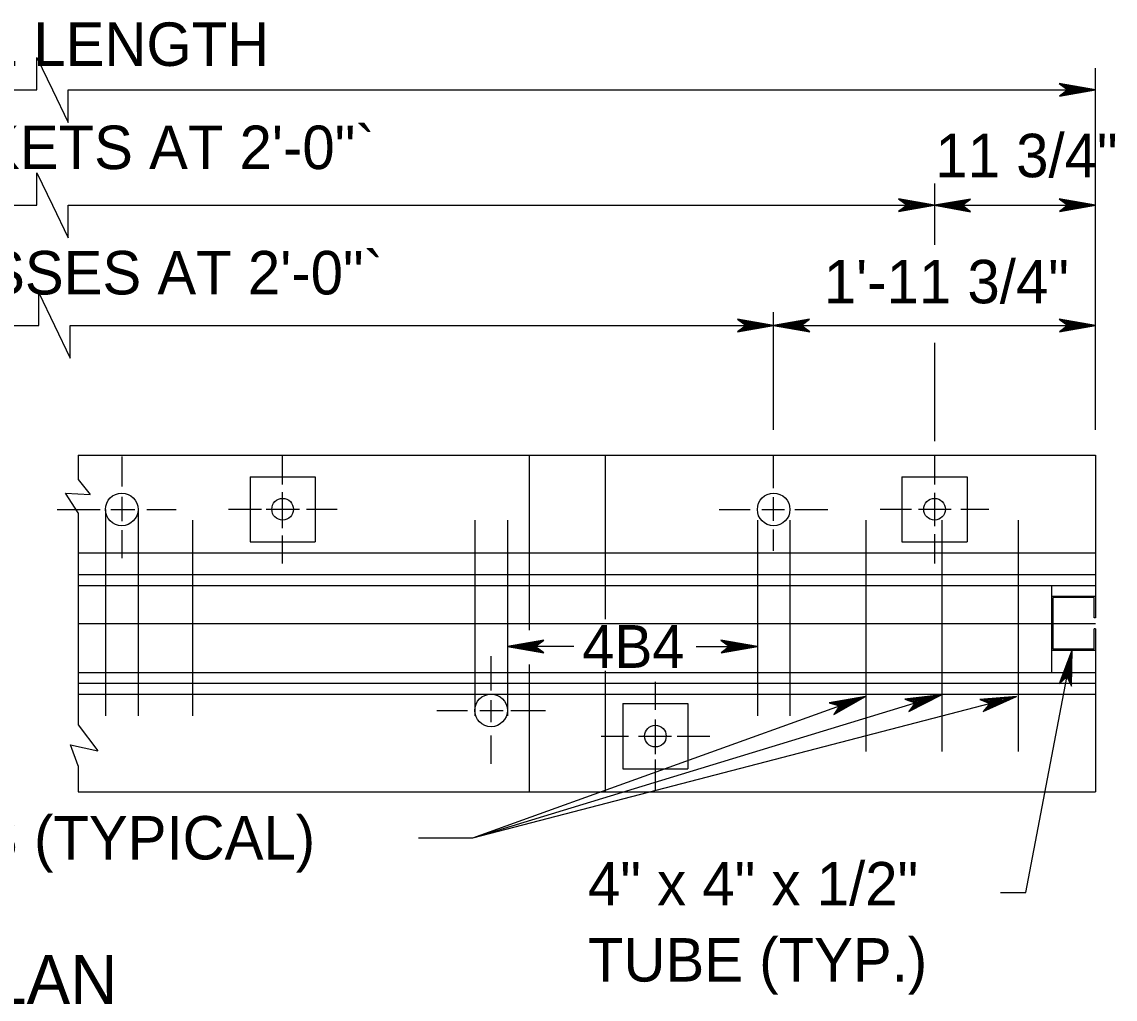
# Model space of a CAD drawing. Extents: x 499883 to 500983, y 499104 to 499764.
# Drawn here: x 500394.2 to 500494.8, y 499311.2 to 499401.1 of the extents above; entities that cross this region are included whole.
import ezdxf

# ---------------------------------------------------------------- set-up
doc = ezdxf.new("R2010")
doc.units = 0
for name, color, linetype in [('1', 7, 'Continuous'), ('24', 7, 'Continuous'), ('5', 7, 'Continuous')]:
    doc.layers.add(name, color=color, linetype=linetype)

msp = doc.modelspace()

# ---------------------------------------------------------------- linework, layer by layer
at = {"layer": '1'}
for p, q in [((500395.61, 499394.84), (500395.61, 499397.84)), ((500395.61, 499397.84), (500397.05, 499394.84)), ((500397.05, 499394.84), (500398.49, 499391.84)), ((500398.49, 499391.84), (500398.49, 499394.84)), ((500395.61, 499384.23), (500395.61, 499387.22)), ((500395.61, 499387.22), (500397.05, 499384.23)), ((500397.05, 499384.23), (500398.49, 499381.23)), ((500398.49, 499381.23), (500398.49, 499384.23)), ((500395.79, 499373.17), (500395.79, 499376.17)), ((500395.79, 499376.17), (500397.23, 499373.17)), ((500397.23, 499373.17), (500398.68, 499370.17)), ((500398.68, 499370.17), (500398.68, 499373.17)), ((500418.22, 499358.54), (500418.22, 499361.25)), ((500418.22, 499354.52), (500418.22, 499357.85)), ((500413.23, 499356.26), (500416.26, 499356.26)), ((500416.71, 499356.26), (500419.77, 499356.26)), ((500420.41, 499356.26), (500423.22, 499356.26)), ((500473.18, 499356.26), (500476.07, 499356.26)), ((500476.71, 499356.26), (500479.72, 499356.26)), ((500480.59, 499356.26), (500483.17, 499356.26)), ((500418.22, 499351.26), (500418.22, 499353.84)), ((500452.5, 499337.8), (500452.5, 499340.39)), ((500452.5, 499333.74), (500452.5, 499336.93)), ((500447.51, 499335.39), (500450.04, 499335.39)), ((500450.95, 499335.39), (500453.97, 499335.39)), ((500454.51, 499335.39), (500457.5, 499335.39)), ((500452.5, 499330.39), (500452.5, 499333.24))]:
    msp.add_line(p, q, dxfattribs=at)
at = {"layer": '24'}
for points in [[(500492.98, 499394.84), (500489.65, 499395.43), (500490.45, 499394.84), (500489.67, 499394.26), (500492.98, 499394.84), (500492.76, 499394.84), (500489.75, 499395.39), (500490.51, 499394.84), (500489.8, 499394.31), (500492.64, 499394.83), (500492.53, 499394.84), (500489.95, 499395.3), (500490.53, 499394.84), (500489.93, 499394.38), (500492.48, 499394.84), (500492.37, 499394.83), (500490.11, 499395.23), (500490.55, 499394.84), (500490.1, 499394.44), (500492.04, 499394.83), (500491.86, 499394.83), (500490.28, 499395.15), (500490.59, 499394.85), (500490.26, 499394.52), (500491.82, 499394.84), (500491.65, 499394.85), (500490.46, 499395.06), (500490.69, 499394.83), (500490.44, 499394.6), (500491.48, 499394.84), (500491.32, 499394.86), (500490.6, 499395), (500490.72, 499394.84), (500490.53, 499394.66), (500491.23, 499394.84), (500490.76, 499394.95), (500490.83, 499394.83), (500490.63, 499394.7), (500491.11, 499394.83), (500490.81, 499394.9), (500490.93, 499394.8), (500490.79, 499394.74), (500490.93, 499394.84), (500490.86, 499394.85)], [(500478.18, 499384.23), (500474.85, 499384.81), (500475.65, 499384.23), (500474.87, 499383.65), (500478.18, 499384.23), (500477.96, 499384.22), (500474.95, 499384.77), (500475.71, 499384.22), (500475, 499383.69), (500477.84, 499384.21), (500477.73, 499384.23), (500475.15, 499384.68), (500475.73, 499384.22), (500475.13, 499383.77), (500477.68, 499384.23), (500477.56, 499384.21), (500475.31, 499384.62), (500475.75, 499384.23), (500475.3, 499383.82), (500477.24, 499384.21), (500477.06, 499384.21), (500475.48, 499384.53), (500475.78, 499384.24), (500475.45, 499383.91), (500477.02, 499384.23), (500476.85, 499384.24), (500475.66, 499384.44), (500475.89, 499384.21), (500475.64, 499383.98), (500476.68, 499384.23), (500476.51, 499384.24), (500475.8, 499384.38), (500475.92, 499384.22), (500475.72, 499384.04), (500476.43, 499384.23), (500475.96, 499384.34), (500476.03, 499384.21), (500475.83, 499384.08), (500476.31, 499384.21), (500476.01, 499384.29), (500476.13, 499384.19), (500475.99, 499384.13), (500476.13, 499384.22), (500476.06, 499384.24)], [(500478.18, 499384.23), (500481.5, 499383.64), (500480.71, 499384.23), (500481.48, 499384.8), (500478.18, 499384.23), (500478.4, 499384.23), (500481.41, 499383.68), (500480.64, 499384.23), (500481.35, 499384.76), (500478.52, 499384.24), (500478.63, 499384.23), (500481.21, 499383.77), (500480.63, 499384.23), (500481.22, 499384.68), (500478.68, 499384.23), (500478.79, 499384.24), (500481.04, 499383.84), (500480.6, 499384.23), (500481.05, 499384.63), (500479.11, 499384.24), (500479.3, 499384.24), (500480.87, 499383.92), (500480.57, 499384.22), (500480.9, 499384.55), (500479.33, 499384.23), (500479.51, 499384.22), (500480.69, 499384.01), (500480.47, 499384.24), (500480.71, 499384.47), (500479.67, 499384.23), (500479.84, 499384.21), (500480.55, 499384.07), (500480.43, 499384.23), (500480.63, 499384.41), (500479.92, 499384.23), (500480.39, 499384.12), (500480.32, 499384.24), (500480.53, 499384.37), (500480.04, 499384.24), (500480.35, 499384.17), (500480.22, 499384.27), (500480.37, 499384.33), (500480.22, 499384.23), (500480.3, 499384.22)], [(500438.89, 499343.63), (500442.24, 499343.04), (500441.44, 499343.63), (500442.23, 499344.22), (500438.89, 499343.63), (500439.12, 499343.64), (500442.15, 499343.09), (500441.38, 499343.64), (500442.09, 499344.17), (500439.24, 499343.65), (500439.35, 499343.63), (500441.95, 499343.17), (500441.36, 499343.64), (500441.96, 499344.1), (500439.4, 499343.63), (500439.51, 499343.65), (500441.78, 499343.24), (500441.34, 499343.63), (500441.79, 499344.04), (500439.83, 499343.65), (500440.02, 499343.65), (500441.61, 499343.33), (500441.3, 499343.63), (500441.64, 499343.96), (500440.06, 499343.63), (500440.24, 499343.62), (500441.43, 499343.42), (500441.2, 499343.65), (500441.45, 499343.88), (500440.4, 499343.63), (500440.57, 499343.62), (500441.29, 499343.48), (500441.17, 499343.64), (500441.36, 499343.82), (500440.66, 499343.63), (500441.12, 499343.52), (500441.06, 499343.65), (500441.26, 499343.78), (500440.77, 499343.65), (500441.08, 499343.57), (500440.95, 499343.68), (500441.1, 499343.74), (500440.95, 499343.64), (500441.03, 499343.63)], [(500461.88, 499343.63), (500458.53, 499344.23), (500459.33, 499343.63), (500458.54, 499343.05), (500461.88, 499343.63), (500461.65, 499343.63), (500458.62, 499344.18), (500459.39, 499343.63), (500458.68, 499343.1), (500461.53, 499343.62), (500461.42, 499343.63), (500458.82, 499344.1), (500459.41, 499343.63), (500458.81, 499343.17), (500461.37, 499343.64), (500461.26, 499343.62), (500458.99, 499344.03), (500459.43, 499343.64), (500458.98, 499343.23), (500460.94, 499343.62), (500460.75, 499343.62), (500459.16, 499343.94), (500459.47, 499343.64), (500459.13, 499343.31), (500460.71, 499343.63), (500460.53, 499343.65), (500459.34, 499343.85), (500459.57, 499343.62), (500459.32, 499343.39), (500460.37, 499343.63), (500460.2, 499343.65), (500459.48, 499343.79), (500459.6, 499343.63), (500459.41, 499343.45), (500460.11, 499343.64), (500459.65, 499343.75), (500459.71, 499343.62), (500459.51, 499343.49), (500460, 499343.62), (500459.69, 499343.69), (500459.82, 499343.59), (500459.67, 499343.53), (500459.82, 499343.63), (500459.74, 499343.64)]]:
    msp.add_lwpolyline(points, dxfattribs=at)
at = {"layer": '5'}
for p, q in [((500492.98, 499363.56), (500492.98, 499396.84)), ((500301.12, 499394.84), (500395.61, 499394.84)), ((500398.49, 499394.84), (500492.98, 499394.84)), ((500478.18, 499386.22), (500478.18, 499380.58)), ((500316.11, 499384.23), (500395.61, 499384.23)), ((500398.49, 499384.23), (500478.18, 499384.23)), ((500478.18, 499384.23), (500492.98, 499384.23)), ((500463.38, 499363.56), (500463.38, 499374.39)), ((500331.09, 499373.17), (500395.79, 499373.17)), ((500398.68, 499373.17), (500463.38, 499373.17)), ((500463.38, 499373.17), (500492.98, 499373.17)), ((500478.18, 499371.59), (500478.18, 499362.54)), ((500399.42, 499361.24), (500492.98, 499361.24)), ((500399.42, 499361.24), (500399.42, 499359)), ((500440.89, 499361.24), (500440.89, 499345.14)), ((500447.89, 499361.24), (500447.89, 499346.14)), ((500463.38, 499358.21), (500463.38, 499361.24)), ((500478.18, 499361.25), (500478.18, 499358.54)), ((500492.98, 499361.24), (500492.98, 499346.26)), ((500403.47, 499358.35), (500403.47, 499361.11)), ((500415.22, 499359.25), (500421.22, 499359.25)), ((500415.22, 499359.25), (500415.22, 499353.26)), ((500421.22, 499359.25), (500421.22, 499353.26)), ((500475.18, 499359.25), (500481.17, 499359.25)), ((500475.18, 499359.25), (500475.18, 499353.26)), ((500481.17, 499359.25), (500481.17, 499353.26)), ((500399.42, 499359), (500400.53, 499357.63)), ((500399.42, 499355.92), (500398.25, 499357.75)), ((500398.25, 499357.75), (500400.53, 499357.63)), ((500403.47, 499355.18), (500403.47, 499357.42)), ((500463.38, 499355.2), (500463.38, 499357.37)), ((500478.18, 499357.76), (500478.18, 499354.7)), ((500397.49, 499356.25), (500401.43, 499356.25)), ((500401.92, 499356.25), (500401.92, 499337.26)), ((500402.42, 499356.25), (500404.63, 499356.25)), ((500404.92, 499356.25), (500404.92, 499337.26)), ((500405.72, 499356.25), (500408.42, 499356.25)), ((500458.38, 499356.25), (500461.21, 499356.25)), ((500462.3, 499356.25), (500464.38, 499356.25)), ((500463.38, 499356.25), (500463.38, 499356.25)), ((500465.34, 499356.25), (500468.37, 499356.25)), ((500399.42, 499355.92), (500399.42, 499336.43)), ((500409.92, 499355.25), (500409.92, 499337.26)), ((500435.9, 499355.25), (500435.9, 499337.26)), ((500438.89, 499355.25), (500438.89, 499337.26)), ((500461.88, 499355.25), (500461.88, 499337.26)), ((500464.87, 499355.25), (500464.87, 499337.26)), ((500471.87, 499355.25), (500471.87, 499333.99)), ((500478.86, 499355.25), (500478.86, 499333.99)), ((500485.86, 499355.25), (500485.86, 499333.99)), ((500403.47, 499351.76), (500403.47, 499354.35)), ((500463.38, 499352.44), (500463.38, 499354.4)), ((500415.22, 499353.26), (500421.22, 499353.26)), ((500475.18, 499353.26), (500481.17, 499353.26)), ((500478.18, 499353.97), (500478.18, 499351.26)), ((500399.42, 499352.25), (500492.98, 499352.25)), ((500399.42, 499350.25), (500492.98, 499350.25)), ((500399.42, 499349.25), (500492.98, 499349.25)), ((500488.98, 499341.26), (500488.98, 499349.25)), ((500492.98, 499348.25), (500488.98, 499348.25)), ((500492.85, 499348.13), (500489.1, 499348.13)), ((500489.1, 499343.38), (500489.1, 499348.13)), ((500492.85, 499346.26), (500492.85, 499348.13)), ((500492.98, 499346.26), (500492.85, 499346.26)), ((500399.42, 499345.76), (500492.98, 499345.76)), ((500492.98, 499345.26), (500492.85, 499345.26)), ((500492.85, 499343.38), (500492.85, 499345.26)), ((500492.98, 499345.26), (500492.98, 499330.27)), ((500445, 499343.63), (500438.89, 499343.63)), ((500456.26, 499343.63), (500461.88, 499343.63)), ((500492.98, 499343.26), (500488.98, 499343.26)), ((500492.85, 499343.38), (500489.1, 499343.38)), ((500437.4, 499339.59), (500437.4, 499342.76)), ((500399.42, 499341.26), (500492.98, 499341.26)), ((500440.89, 499341.97), (500440.89, 499330.27)), ((500447.89, 499341.4), (500447.89, 499330.27)), ((500399.42, 499340.26), (500492.98, 499340.26)), ((500399.42, 499339.26), (500492.98, 499339.26)), ((500435.71, 499326.04), (500478.81, 499339.19)), ((500435.71, 499326.04), (500471.82, 499339.04)), ((500437.4, 499336.67), (500437.4, 499338.69)), ((500449.51, 499338.39), (500455.5, 499338.39)), ((500449.51, 499338.39), (500449.51, 499332.39)), ((500455.5, 499338.39), (500455.5, 499332.39)), ((500432.4, 499337.76), (500435.21, 499337.76)), ((500436.36, 499337.76), (500438.51, 499337.76)), ((500439.21, 499337.76), (500442.39, 499337.76)), ((500399.42, 499336.43), (500401.21, 499334.03)), ((500437.4, 499332.85), (500437.4, 499335.46)), ((500399.42, 499332.67), (500398.71, 499334.6)), ((500398.71, 499334.6), (500401.21, 499334.03)), ((500399.42, 499332.67), (500399.42, 499330.27)), ((500449.51, 499332.39), (500455.5, 499332.39)), ((500399.42, 499330.27), (500492.98, 499330.27))]:
    msp.add_line(p, q, dxfattribs=at)
for points in [[(500492.98, 499384.23), (500489.65, 499384.81), (500490.45, 499384.23), (500489.67, 499383.65), (500492.98, 499384.23), (500492.76, 499384.22), (500489.75, 499384.77), (500490.51, 499384.22), (500489.8, 499383.69), (500492.64, 499384.21), (500492.53, 499384.23), (500489.95, 499384.68), (500490.53, 499384.22), (500489.93, 499383.77), (500492.48, 499384.23), (500492.37, 499384.21), (500490.11, 499384.62), (500490.55, 499384.23), (500490.1, 499383.82), (500492.04, 499384.21), (500491.86, 499384.21), (500490.28, 499384.53), (500490.59, 499384.24), (500490.26, 499383.91), (500491.82, 499384.23), (500491.65, 499384.24), (500490.46, 499384.44), (500490.69, 499384.21), (500490.44, 499383.98), (500491.48, 499384.23), (500491.32, 499384.24), (500490.6, 499384.38), (500490.72, 499384.22), (500490.53, 499384.04), (500491.23, 499384.23), (500490.76, 499384.34), (500490.83, 499384.21), (500490.63, 499384.08), (500491.11, 499384.21), (500490.81, 499384.29), (500490.93, 499384.19), (500490.79, 499384.13), (500490.93, 499384.22), (500490.86, 499384.24)], [(500463.38, 499373.17), (500460.05, 499373.76), (500460.85, 499373.17), (500460.07, 499372.59), (500463.38, 499373.17), (500463.15, 499373.17), (500460.14, 499373.72), (500460.91, 499373.16), (500460.2, 499372.64), (500463.04, 499373.16), (500462.92, 499373.17), (500460.35, 499373.63), (500460.92, 499373.17), (500460.33, 499372.71), (500462.87, 499373.17), (500462.76, 499373.16), (500460.51, 499373.56), (500460.95, 499373.17), (500460.5, 499372.77), (500462.44, 499373.16), (500462.25, 499373.16), (500460.68, 499373.48), (500460.98, 499373.18), (500460.65, 499372.85), (500462.22, 499373.17), (500462.04, 499373.18), (500460.86, 499373.39), (500461.09, 499373.16), (500460.84, 499372.93), (500461.88, 499373.17), (500461.71, 499373.19), (500461, 499373.32), (500461.12, 499373.16), (500460.92, 499372.99), (500461.63, 499373.17), (500461.16, 499373.28), (500461.23, 499373.16), (500461.03, 499373.03), (500461.51, 499373.16), (500461.2, 499373.23), (500461.33, 499373.13), (500461.19, 499373.07), (500461.33, 499373.16), (500461.26, 499373.18)], [(500463.38, 499373.17), (500466.7, 499372.58), (500465.91, 499373.17), (500466.68, 499373.75), (500463.38, 499373.17), (500463.6, 499373.18), (500466.61, 499372.63), (500465.84, 499373.18), (500466.55, 499373.7), (500463.72, 499373.19), (500463.83, 499373.17), (500466.4, 499372.71), (500465.83, 499373.18), (500466.42, 499373.63), (500463.88, 499373.17), (500463.99, 499373.19), (500466.24, 499372.78), (500465.8, 499373.17), (500466.25, 499373.58), (500464.31, 499373.19), (500464.5, 499373.19), (500466.07, 499372.87), (500465.77, 499373.16), (500466.1, 499373.49), (500464.53, 499373.17), (500464.71, 499373.16), (500465.89, 499372.96), (500465.66, 499373.19), (500465.91, 499373.42), (500464.87, 499373.17), (500465.04, 499373.16), (500465.75, 499373.02), (500465.63, 499373.18), (500465.83, 499373.36), (500465.12, 499373.17), (500465.59, 499373.06), (500465.52, 499373.19), (500465.73, 499373.32), (500465.24, 499373.19), (500465.55, 499373.11), (500465.42, 499373.21), (500465.56, 499373.27), (500465.42, 499373.18), (500465.49, 499373.16)], [(500492.98, 499373.17), (500489.65, 499373.76), (500490.45, 499373.17), (500489.67, 499372.59), (500492.98, 499373.17), (500492.76, 499373.17), (500489.75, 499373.72), (500490.51, 499373.16), (500489.8, 499372.64), (500492.64, 499373.16), (500492.53, 499373.17), (500489.95, 499373.63), (500490.53, 499373.17), (500489.93, 499372.71), (500492.48, 499373.17), (500492.37, 499373.16), (500490.11, 499373.56), (500490.55, 499373.17), (500490.1, 499372.77), (500492.04, 499373.16), (500491.86, 499373.16), (500490.28, 499373.48), (500490.59, 499373.18), (500490.26, 499372.85), (500491.82, 499373.17), (500491.65, 499373.18), (500490.46, 499373.39), (500490.69, 499373.16), (500490.44, 499372.93), (500491.48, 499373.17), (500491.32, 499373.19), (500490.6, 499373.32), (500490.72, 499373.16), (500490.53, 499372.99), (500491.23, 499373.17), (500490.76, 499373.28), (500490.83, 499373.16), (500490.63, 499373.03), (500491.11, 499373.16), (500490.81, 499373.23), (500490.93, 499373.13), (500490.79, 499373.07), (500490.93, 499373.16), (500490.86, 499373.18)], [(500484.26, 499321), (500486.56, 499321), (500490.83, 499343.35)], [(500490.83, 499343.35), (500489.63, 499340.19), (500490.35, 499340.86), (500490.78, 499339.99), (500490.83, 499343.35), (500490.79, 499343.13), (500489.69, 499340.28), (500490.37, 499340.92), (500490.76, 499340.13), (500490.78, 499343.01), (500490.74, 499342.91), (500489.81, 499340.46), (500490.38, 499340.94), (500490.71, 499340.27), (500490.73, 499342.86), (500490.73, 499342.74), (500489.91, 499340.61), (500490.37, 499340.96), (500490.69, 499340.45), (500490.67, 499342.43), (500490.64, 499342.24), (500490.02, 499340.76), (500490.37, 499341), (500490.63, 499340.61), (500490.61, 499342.22), (500490.57, 499342.04), (500490.15, 499340.92), (500490.42, 499341.1), (500490.59, 499340.81), (500490.55, 499341.88), (500490.5, 499341.72), (500490.23, 499341.05), (500490.41, 499341.13), (500490.55, 499340.91), (500490.5, 499341.63), (500490.31, 499341.2), (500490.44, 499341.24), (500490.53, 499341.01), (500490.5, 499341.51), (500490.36, 499341.23), (500490.49, 499341.33), (500490.52, 499341.18), (500490.45, 499341.34), (500490.42, 499341.27)], [(500478.81, 499339.19), (500475.46, 499338.78), (500476.39, 499338.45), (500475.81, 499337.67), (500478.81, 499339.19), (500478.6, 499339.12), (500475.56, 499338.76), (500476.45, 499338.46), (500475.93, 499337.75), (500478.49, 499339.07), (500478.38, 499339.05), (500475.78, 499338.74), (500476.46, 499338.46), (500476.03, 499337.86), (500478.33, 499339.04), (500478.23, 499338.99), (500475.95, 499338.72), (500476.49, 499338.48), (500476.18, 499337.96), (500477.92, 499338.9), (500477.74, 499338.84), (500476.14, 499338.69), (500476.52, 499338.5), (500476.3, 499338.08), (500477.7, 499338.85), (500477.53, 499338.81), (500476.34, 499338.66), (500476.62, 499338.5), (500476.45, 499338.21), (500477.38, 499338.75), (500477.21, 499338.72), (500476.49, 499338.64), (500476.65, 499338.52), (500476.52, 499338.29), (500477.13, 499338.68), (500476.66, 499338.65), (500476.76, 499338.54), (500476.6, 499338.36), (500477.03, 499338.63), (500476.71, 499338.61), (500476.87, 499338.55), (500476.74, 499338.45), (500476.85, 499338.58), (500476.78, 499338.58)], [(500430.71, 499326.04), (500435.71, 499326.04), (500485.72, 499339.04)], [(500471.82, 499339.04), (500468.5, 499338.46), (500469.44, 499338.18), (500468.91, 499337.37), (500471.82, 499339.04), (500471.62, 499338.96), (500468.6, 499338.46), (500469.5, 499338.2), (500469.02, 499337.46), (500471.51, 499338.91), (500471.4, 499338.88), (500468.82, 499338.44), (500469.52, 499338.2), (500469.11, 499337.57), (500471.35, 499338.87), (500471.25, 499338.81), (500469, 499338.43), (500469.54, 499338.22), (500469.26, 499337.68), (500470.95, 499338.71), (500470.78, 499338.64), (500469.18, 499338.41), (500469.57, 499338.24), (500469.37, 499337.81), (500470.74, 499338.65), (500470.57, 499338.6), (500469.38, 499338.39), (500469.68, 499338.25), (500469.52, 499337.95), (500470.42, 499338.53), (500470.25, 499338.49), (500469.54, 499338.38), (500469.7, 499338.27), (500469.58, 499338.03), (500470.18, 499338.45), (500469.7, 499338.39), (500469.81, 499338.3), (500469.66, 499338.11), (500470.07, 499338.39), (500469.76, 499338.36), (500469.92, 499338.31), (500469.8, 499338.2), (500469.9, 499338.34), (500469.83, 499338.33)], [(500485.72, 499339.04), (500482.35, 499338.77), (500483.27, 499338.4), (500482.66, 499337.65), (500485.72, 499339.04), (500485.5, 499338.98), (500482.45, 499338.75), (500483.33, 499338.41), (500482.78, 499337.72), (500485.39, 499338.94), (500485.28, 499338.92), (500482.67, 499338.72), (500483.35, 499338.41), (500482.88, 499337.83), (500485.23, 499338.91), (500485.13, 499338.87), (500482.84, 499338.69), (500483.37, 499338.43), (500483.04, 499337.92), (500484.82, 499338.79), (500484.64, 499338.74), (500483.03, 499338.66), (500483.4, 499338.44), (500483.16, 499338.04), (500484.6, 499338.75), (500484.42, 499338.71), (500483.22, 499338.61), (500483.5, 499338.44), (500483.32, 499338.16), (500484.27, 499338.66), (500484.1, 499338.64), (500483.38, 499338.59), (500483.53, 499338.46), (500483.39, 499338.24), (500484.02, 499338.6), (500483.55, 499338.59), (500483.64, 499338.48), (500483.48, 499338.31), (500483.91, 499338.55), (500483.6, 499338.55), (500483.75, 499338.48), (500483.62, 499338.39), (500483.74, 499338.52), (500483.66, 499338.51)]]:
    msp.add_lwpolyline(points, dxfattribs=at)
for centre, radius in [((500403.42, 499356.25), 1.5), ((500418.22, 499356.26), 0.999), ((500463.38, 499356.25), 1.5), ((500478.18, 499356.26), 0.999), ((500437.39, 499337.76), 1.5), ((500452.5, 499335.39), 0.999)]:
    msp.add_circle(centre, radius, dxfattribs=at)

# ---------------------------------------------------------------- texts
for s, height, p in [('NOMINAL LENGTH', 4, (500369.43, 499397.05)), ('10-ANCHOR POCKETS AT 2\'-0"`', 4, (500346.49, 499387.56)), ('11 3/4"', 4, (500478.25, 499386.81)), ('9-ANCHOR RECESSES AT 2\'-0"`', 4, (500346.66, 499376.03)), ('1\'-11 3/4"', 4, (500467.99, 499375.21)), ('4B4', 3.937, (500445.79, 499341.67)), ('STIRRUPS (TYPICAL)', 4, (500366.82, 499324.04)), ('4" x 4" x 1/2"', 4, (500446.3, 499319.81)), ('TUBE (TYP.)', 4, (500446.3, 499312.81)), ('PLAN', 4.5, (500387.31, 499310.74))]:
    msp.add_text(s, height=height, dxfattribs=at).set_placement(p)

doc.saveas('drawing.dxf')
